(* Logix 5000 project; controller MCMR_v15 vendor 1 type 14 code 51 rev 15.1; software revision 15.02 *)

TASK MainTask (continuous, watchdog 500 ms) : MainProgram

MODULES
   Local : vendor 1 type 14 code 51 (ICP 0, rev 15.1)
      Local_ENBT : 1756-ENBT (Ethernet 105.102.0.224, ICP 3, rev 2.4)
         Remote_ENBT : 1756-ENBT (Ethernet 105.102.0.205, rev 1.6, Output RPI 10 ms)
            MCMR : vendor 1 type 0 code 15 (ICP 1, rev 1.1, Output RPI 5 ms)
END_MODULES

TYPE MCMRBlockStats :   // This object is used to store the block transfer statistics for the MVI56-MCMR module.
STRUCT
   Read : INT;   // Total number of read block transfers
   Write : INT;   // Total number of write block transfers
   Parse : INT;   // Total number of blocks parsed
   Event : INT;   // Total number of event blocks received
   Cmd : INT;   // Total number of command blocks received
   Err : INT;   // Total number of block transfer errors
END_STRUCT
END_TYPE

TYPE MCMRCmdControl :   // Controlling the Modbus Commands
STRUCT
   CmdTrigger : BOOL;   // Command Trigger
   CmdControlData : INT[21];   // Command Control Data
   CmdControlResp : INT[5];   // Command Control Response
   CmdErrTrigger : BOOL;   // Command Error Trigger
   CmdErrData : INT[102];   // Command Error Data
END_STRUCT
END_TYPE

TYPE MCMRCONTROL :   // Tags used for special blocks
STRUCT
   ColdBoot : BOOL;   // Module hardware reset
   WarmBoot : BOOL;   // Module configuration reset
   CmdControlP1 : MCMRCmdControl;   // Command Control for Port 1
   CmdControlP2 : MCMRCmdControl;   // Command Control for Port 2
   EventTriggerP1 : BOOL;   // Triggers the Event Command.
   EventTriggerP2 : BOOL;   // Triggers the Event Command.
   EventCmdP1 : MCMREventCmd[100];   // Event Command for Port 1
   EventCmdP2 : MCMREventCmd[100];   // Event Command for Port 2
   EventCmdRespP1 : INT[5];   // Event Command Response for Port 1
   EventCmdRespP2 : INT[5];   // Event Command Response for Port 2
END_STRUCT
END_TYPE

TYPE MCMRDATA :   // This object contains the Read & Write Data Arrays.
STRUCT
   ReadData : INT[600];   // Data read from module
   WriteData : INT[600];   // Data to write to module
END_STRUCT
END_TYPE

TYPE MCMREventCmd :   // This object is used to contain the attributes to define a master command. An array of these objects is used for each port.
STRUCT
   Enable : INT;   // 0=Disable,1=Continuous,2=Event Command
   IntAddress : INT;   // Module's internal address associated with the command
   PollInt : INT;   // Not used.
   Count : INT;   // Number of registers associated with the command
   Swap : INT;   // Swap code used with command
   Device : INT;   // Device index in Device Table to associate with the command
   Func : INT;   // Function code for the command
   DevAddress : INT;   // Address in device associated with the command
END_STRUCT
END_TYPE

TYPE MCMRInitOutputData :   // Used to bring the Module into a known state after a restart operation.
STRUCT
   InitOutBlkIDLim : INT;   // Block Index Limit for ReadData size of the array
END_STRUCT
END_TYPE

TYPE MCMRModuleDef :   // This object contains variables to be used with the module and status data related to the module.
STRUCT
   DATA : MCMRDATA;   // Read Data and Write Data
   STATUS : MCMRSTATUS;   // Status information in each read block
   CONTROL : MCMRCONTROL;   // Command Control Object
   UTIL : MCMRUTIL;   // Backplane Object
END_STRUCT
END_TYPE

TYPE MCMRPortStats :   // This object is used to store the port statistics for an MVI56-MCMR port.
STRUCT
   PortTrigger : BOOL;   // Triggers port status reading
   CmdReq : INT;   // Total number of command list requests sent
   CmdResp : INT;   // Total number of command list responses received
   CmdErr : INT;   // Total number of command list errors
   Requests : INT;   // Total number of requests for port
   Responses : INT;   // Total number of responses for port
   ErrSent : INT;   // Total number of errors sent
   ErrRec : INT;   // Total number of errors received
   SlaveStats : SINT[250];   // Port Slave status values
END_STRUCT
END_TYPE

TYPE MCMRSTATUS :   // This status data is returned on each read block and can be used to detect proper module operation.
STRUCT
   PassCnt : INT;   // Program cycle counter
   Product : INT[2];   // Product Name
   Rev : INT[2];   // Revision Level Number
   OP : INT[2];   // Operating Level Number
   Run : INT[2];   // Run Number
   Port1Stats : MCMRPortStats;   // Port error statistics for Port 1
   Port2Stats : MCMRPortStats;   // Port error statistics for Port 2
   Block : MCMRBlockStats;   // Block transfer statistics
   Port1CurrentErr : INT;   // Current error/index for Port 1
   Port1LastErr : INT;   // Last error/index for Port 1
   Port2CurrentErr : INT;   // Current error/index for Port 2
   Port2LastErr : INT;   // Last error/index for Port 2
   StatusMsgData : INT[46];   // Triggers status message data
   StatusTrigger : BOOL;   // Triggers Status reading.
END_STRUCT
END_TYPE

TYPE MCMRUTIL :   // This object stores all the variables required for data transfer operation between the module and the controller.
STRUCT
   LastRead : INT;   // Index of last read block
   LastWrite : INT;   // Index of last write block
   BlockIndex : INT;   // Computed block offset for data table
   ReadDataSize : DINT;   // Size of Read Data Array
   WriteDataSize : DINT;   // Size of Write Data Array
   RBTSremainder : INT;   // Computed remainder from Read Data Array size
   WBTSremainder : INT;   // Computed remainder from Write Data Array size
   MaxReadBlock : DINT;   // Maximum read block
   MaxWriteBlock : DINT;   // Maximum write block
   InitOutputData : MCMRInitOutputData;   // This is to initialize output data module reads data from PLC
END_STRUCT
END_TYPE

VAR_GLOBAL   (* controller tags *)
   CmdControlP1_MSG : MESSAGE;
        MessageParameters(ServiceCode := 16#0010, LocalElement := MCMR.CONTROL.CmdControlP1.CmdControlData[0], ...)
   CmdControlP2_MSG : MESSAGE;
        MessageParameters(ServiceCode := 16#0010, LocalElement := MCMR.CONTROL.CmdControlP2.CmdControlData[0], ...)
   CmdControlRespP1_MSG : MESSAGE;
        MessageParameters(ServiceCode := 16#000e, DestinationTag := MCMR.CONTROL.CmdControlP1.CmdControlResp[0], ...)
   CmdControlRespP2_MSG : MESSAGE;
        MessageParameters(ServiceCode := 16#000e, DestinationTag := MCMR.CONTROL.CmdControlP2.CmdControlResp[0], ...)
   CmdErrorP1_MSG : MESSAGE;
        MessageParameters(ServiceCode := 16#000e, DestinationTag := MCMR.CONTROL.CmdControlP1.CmdErrData[0], ...)
   CmdErrorP2_MSG : MESSAGE;
        MessageParameters(ServiceCode := 16#000e, DestinationTag := MCMR.CONTROL.CmdControlP2.CmdErrData[0], ...)
   EventCmdP1_MSG : MESSAGE;
        MessageParameters(ServiceCode := 16#0010, LocalElement := MCMR.CONTROL.EventCmdP1[0], ...)
   EventCmdP2_MSG : MESSAGE;
        MessageParameters(ServiceCode := 16#0010, LocalElement := MCMR.CONTROL.EventCmdP2[0], ...)
   EventCmdRespP1_MSG : MESSAGE;
        MessageParameters(ServiceCode := 16#000e, DestinationTag := MCMR.CONTROL.EventCmdRespP1[0], ...)
   EventCmdRespP2_MSG : MESSAGE;
        MessageParameters(ServiceCode := 16#000e, DestinationTag := MCMR.CONTROL.EventCmdRespP2[0], ...)
   MCMR : MCMRModuleDef;
   MJFAULTS : DINT[12] := ([0] := -731009779, [1] := 207094, [3] := 808632201, [4] := 207000);
   ModuleStatus_MSG : MESSAGE;
        MessageParameters(ServiceCode := 16#000e, DestinationTag := MCMR.STATUS.StatusMsgData[0], ...)
   SlaveStatusP1_MSG : MESSAGE;
        MessageParameters(ServiceCode := 16#000e, DestinationTag := MCMR.STATUS.Port1Stats.SlaveStats[0], ...)
   SlaveStatusP2_MSG : MESSAGE;
        MessageParameters(ServiceCode := 16#000e, DestinationTag := MCMR.STATUS.Port2Stats.SlaveStats[0], ...)
END_VAR

PROGRAM MainProgram   (* main routine MainRoutine *)

ROUTINE MainRoutine   (* ladder *)
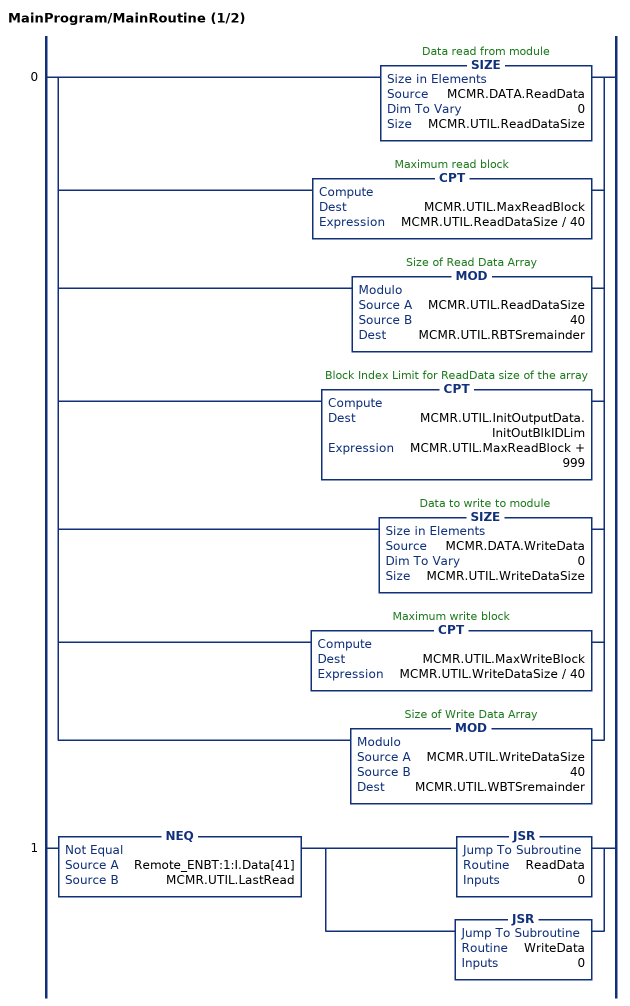
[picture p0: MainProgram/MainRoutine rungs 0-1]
   0: [SIZE(MCMR.DATA.ReadData,0,MCMR.UTIL.ReadDataSize) ,CPT(MCMR.UTIL.MaxReadBlock,MCMR.UTIL.ReadDataSize / 40) ,MOD(MCMR.UTIL.ReadDataSize,40,MCMR.UTIL.RBTSremainder) ,CPT(MCMR.UTIL.InitOutputData.InitOutBlkIDLim,MCMR.UTIL.MaxReadBlock + 999) ,SIZE(MCMR.DATA.WriteData,0,MCMR.UTIL.WriteDataSize) ,CPT(MCMR.UTIL.MaxWriteBlock,MCMR.UTIL.WriteDataSize / 40) ,MOD(MCMR.UTIL.WriteDataSize,40,MCMR.UTIL.WBTSremainder) ];
   1: NEQ(Remote_ENBT:1:I.Data[41],MCMR.UTIL.LastRead)[JSR(ReadData,0) ,JSR(WriteData,0) ];
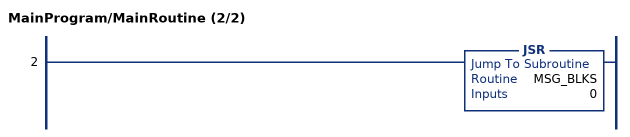
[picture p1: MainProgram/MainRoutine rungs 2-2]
   2: JSR(MSG_BLKS,0);
END_ROUTINE

ROUTINE MSG_BLKS   (* ladder *)
// This routine handles all the MSG blocks used by the MCMR module
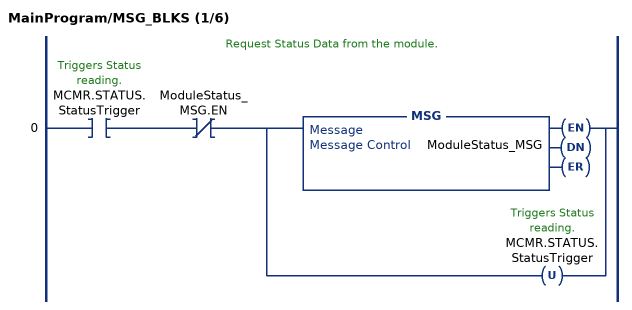
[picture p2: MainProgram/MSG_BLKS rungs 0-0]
   // Request Status Data from the module.
   0: XIC(MCMR.STATUS.StatusTrigger)XIO(ModuleStatus_MSG.EN)[MSG(ModuleStatus_MSG) ,OTU(MCMR.STATUS.StatusTrigger) ];
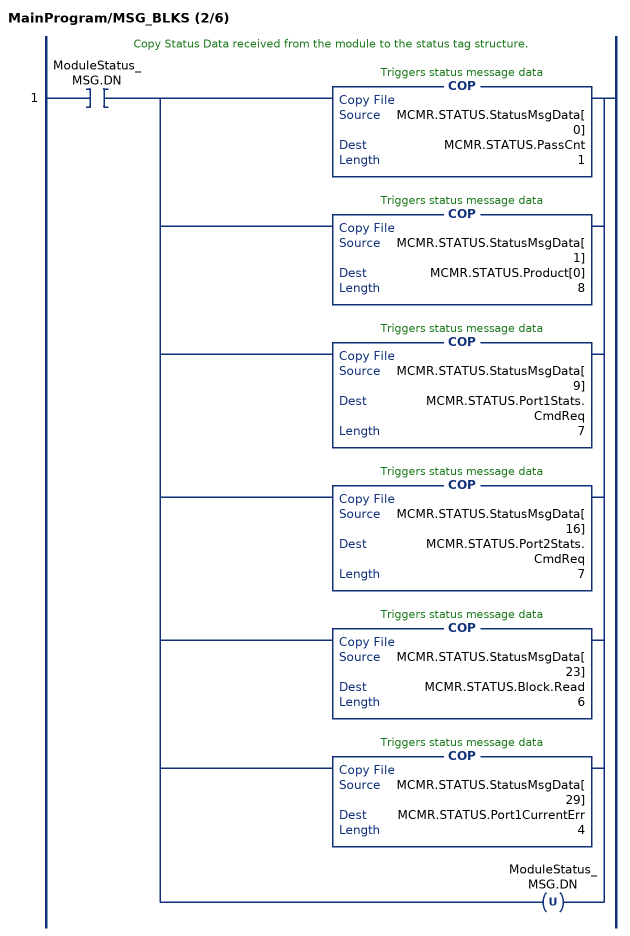
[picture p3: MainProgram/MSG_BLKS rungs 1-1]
   // Copy Status Data received from the module to the status tag structure.
   1: XIC(ModuleStatus_MSG.DN)[COP(MCMR.STATUS.StatusMsgData[0],MCMR.STATUS.PassCnt,1) ,COP(MCMR.STATUS.StatusMsgData[1],MCMR.STATUS.Product[0],8) ,COP(MCMR.STATUS.StatusMsgData[9],MCMR.STATUS.Port1Stats.CmdReq,7) ,COP(MCMR.STATUS.StatusMsgData[16],MCMR.STATUS.Port2Stats.CmdReq,7) ,COP(MCMR.STATUS.StatusMsgData[23],MCMR.STATUS.Block.Read,6) ,COP(MCMR.STATUS.StatusMsgData[29],MCMR.STATUS.Port1CurrentErr,4) ,OTU(ModuleStatus_MSG.DN) ];
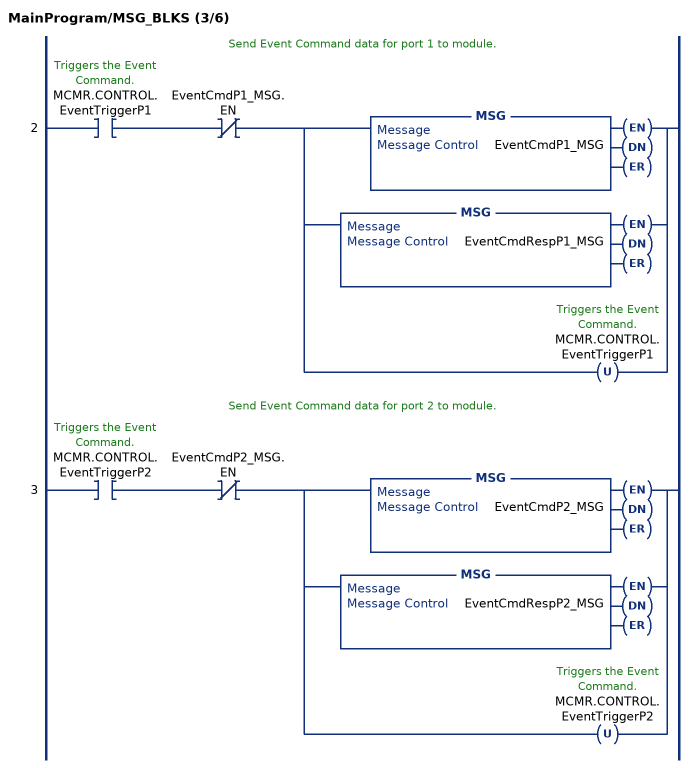
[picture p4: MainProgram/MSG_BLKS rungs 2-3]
   // Send Event Command data for port 1 to module.
   2: XIC(MCMR.CONTROL.EventTriggerP1)XIO(EventCmdP1_MSG.EN)[MSG(EventCmdP1_MSG) ,MSG(EventCmdRespP1_MSG) ,OTU(MCMR.CONTROL.EventTriggerP1) ];
   // Send Event Command data for port 2 to module.
   3: XIC(MCMR.CONTROL.EventTriggerP2)XIO(EventCmdP2_MSG.EN)[[MSG(EventCmdP2_MSG) ,MSG(EventCmdRespP2_MSG) ] ,OTU(MCMR.CONTROL.EventTriggerP2) ];
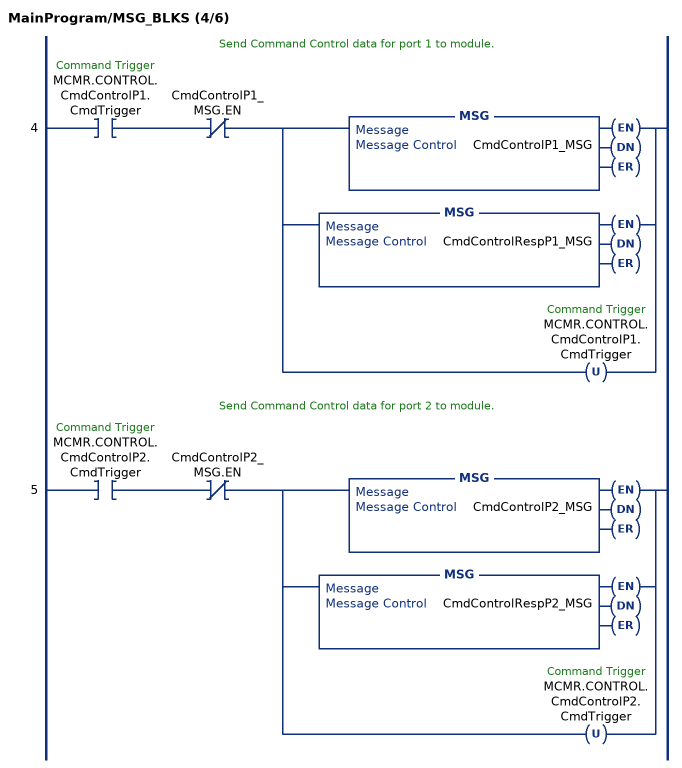
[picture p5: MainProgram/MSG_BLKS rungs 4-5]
   // Send Command Control data for port 1 to module.
   4: XIC(MCMR.CONTROL.CmdControlP1.CmdTrigger)XIO(CmdControlP1_MSG.EN)[[MSG(CmdControlP1_MSG) ,MSG(CmdControlRespP1_MSG) ] ,OTU(MCMR.CONTROL.CmdControlP1.CmdTrigger) ];
   // Send Command Control data for port 2 to module.
   5: XIC(MCMR.CONTROL.CmdControlP2.CmdTrigger)XIO(CmdControlP2_MSG.EN)[[MSG(CmdControlP2_MSG) ,MSG(CmdControlRespP2_MSG) ] ,OTU(MCMR.CONTROL.CmdControlP2.CmdTrigger) ];
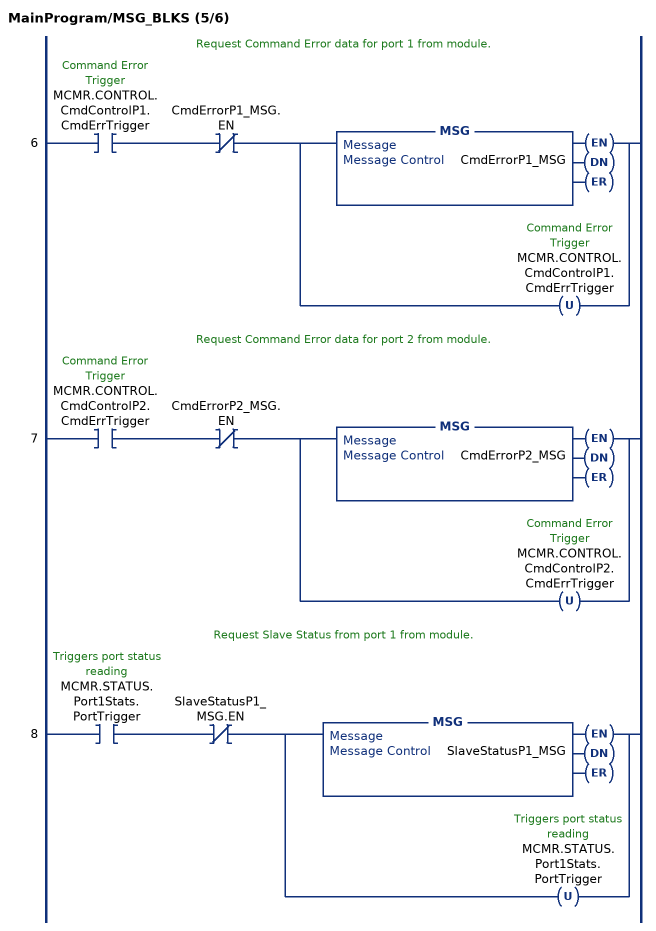
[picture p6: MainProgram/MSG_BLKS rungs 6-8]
   // Request Command Error data for port 1 from module.
   6: XIC(MCMR.CONTROL.CmdControlP1.CmdErrTrigger)XIO(CmdErrorP1_MSG.EN)[MSG(CmdErrorP1_MSG) ,OTU(MCMR.CONTROL.CmdControlP1.CmdErrTrigger) ];
   // Request Command Error data for port 2 from module.
   7: XIC(MCMR.CONTROL.CmdControlP2.CmdErrTrigger)XIO(CmdErrorP2_MSG.EN)[MSG(CmdErrorP2_MSG) ,OTU(MCMR.CONTROL.CmdControlP2.CmdErrTrigger) ];
   // Request Slave Status from port 1 from module.
   8: XIC(MCMR.STATUS.Port1Stats.PortTrigger)XIO(SlaveStatusP1_MSG.EN)[MSG(SlaveStatusP1_MSG) ,OTU(MCMR.STATUS.Port1Stats.PortTrigger) ];
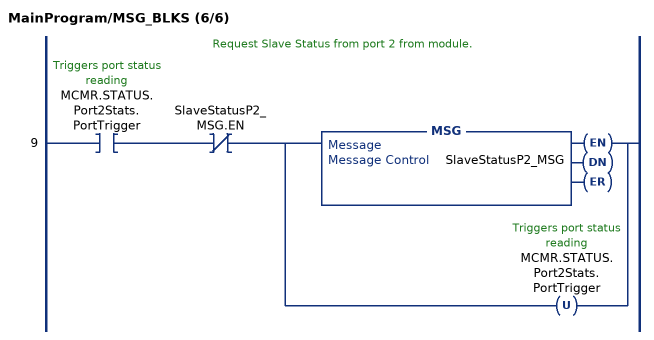
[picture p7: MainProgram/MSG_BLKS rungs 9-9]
   // Request Slave Status from port 2 from module.
   9: XIC(MCMR.STATUS.Port2Stats.PortTrigger)XIO(SlaveStatusP2_MSG.EN)[MSG(SlaveStatusP2_MSG) ,OTU(MCMR.STATUS.Port2Stats.PortTrigger) ];
END_ROUTINE

ROUTINE ReadData   (* ladder *)
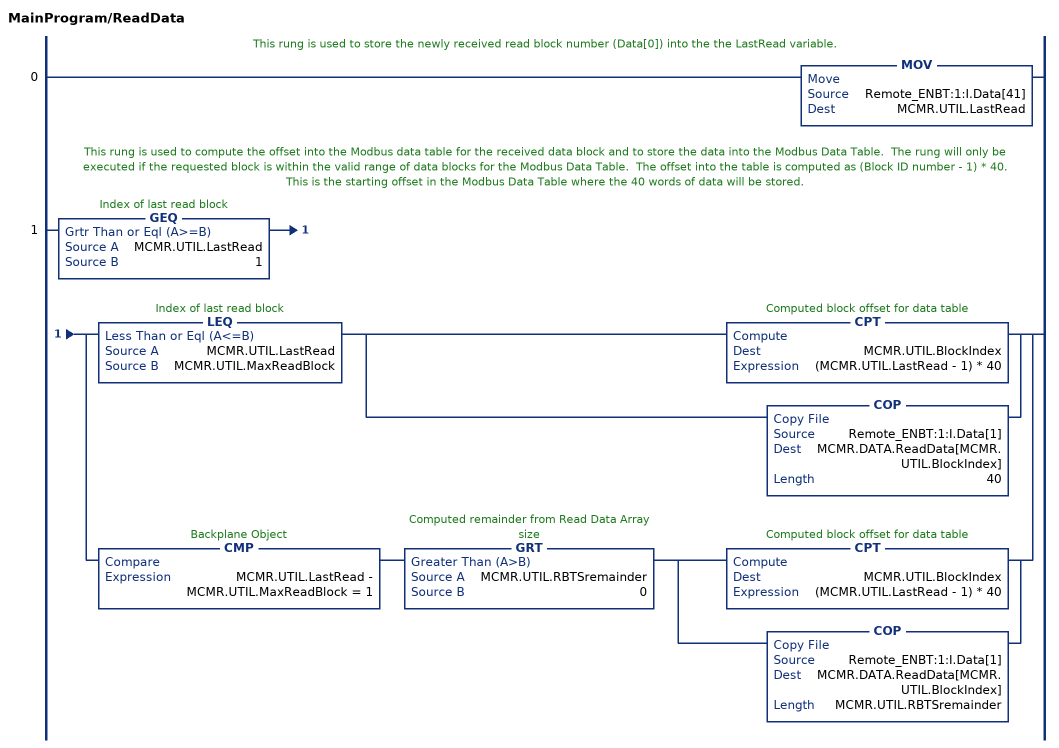
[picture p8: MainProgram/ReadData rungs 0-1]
   // This rung is used to store the newly received read block number (Data[0]) into the the LastRead variable.
   0: MOV(Remote_ENBT:1:I.Data[41],MCMR.UTIL.LastRead);
   // This rung is used to compute the offset into the Modbus data table for the received data block and to store the data into the Modbus Data Table.  The rung will only be executed if the requested block is within the valid range of data blocks for the Modbus Data Table.  The offset into the table is computed as (Block ID number - 1) * 40.  This is the starting offset in the Modbus Data Table where the 40 words of data will be stored.
   1: GEQ(MCMR.UTIL.LastRead,1)[LEQ(MCMR.UTIL.LastRead,MCMR.UTIL.MaxReadBlock) [CPT(MCMR.UTIL.BlockIndex,(MCMR.UTIL.LastRead - 1) * 40) ,COP(Remote_ENBT:1:I.Data[1],MCMR.DATA.ReadData[MCMR.UTIL.BlockIndex],40) ] ,CMP(MCMR.UTIL.LastRead - MCMR.UTIL.MaxReadBlock = 1) GRT(MCMR.UTIL.RBTSremainder,0) [CPT(MCMR.UTIL.BlockIndex,(MCMR.UTIL.LastRead - 1) * 40) ,COP(Remote_ENBT:1:I.Data[1],MCMR.DATA.ReadData[MCMR.UTIL.BlockIndex],MCMR.UTIL.RBTSremainder) ] ];
END_ROUTINE

ROUTINE WriteData   (* ladder *)
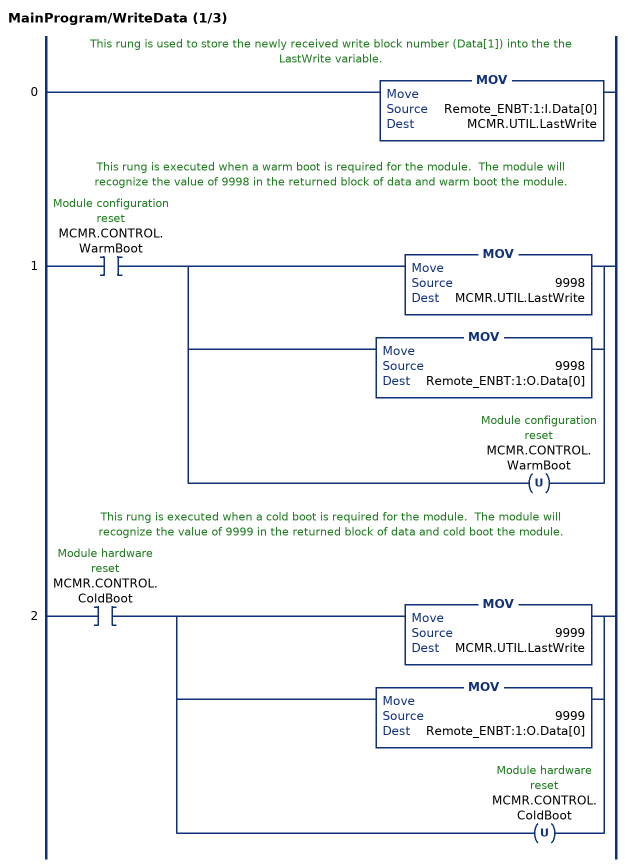
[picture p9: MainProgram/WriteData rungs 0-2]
   // This rung is used to store the newly received write block number (Data[1]) into the the LastWrite variable.
   0: MOV(Remote_ENBT:1:I.Data[0],MCMR.UTIL.LastWrite);
   // This rung is executed when a warm boot is required for the module.  The module will recognize the value of 9998 in the returned block of data and warm boot the module.
   1: XIC(MCMR.CONTROL.WarmBoot)[MOV(9998,MCMR.UTIL.LastWrite) ,MOV(9998,Remote_ENBT:1:O.Data[0]) ,OTU(MCMR.CONTROL.WarmBoot) ];
   // This rung is executed when a cold boot is required for the module.  The module will recognize the value of 9999 in the returned block of data and cold boot the module.
   2: XIC(MCMR.CONTROL.ColdBoot)[MOV(9999,MCMR.UTIL.LastWrite) ,MOV(9999,Remote_ENBT:1:O.Data[0]) ,OTU(MCMR.CONTROL.ColdBoot) ];
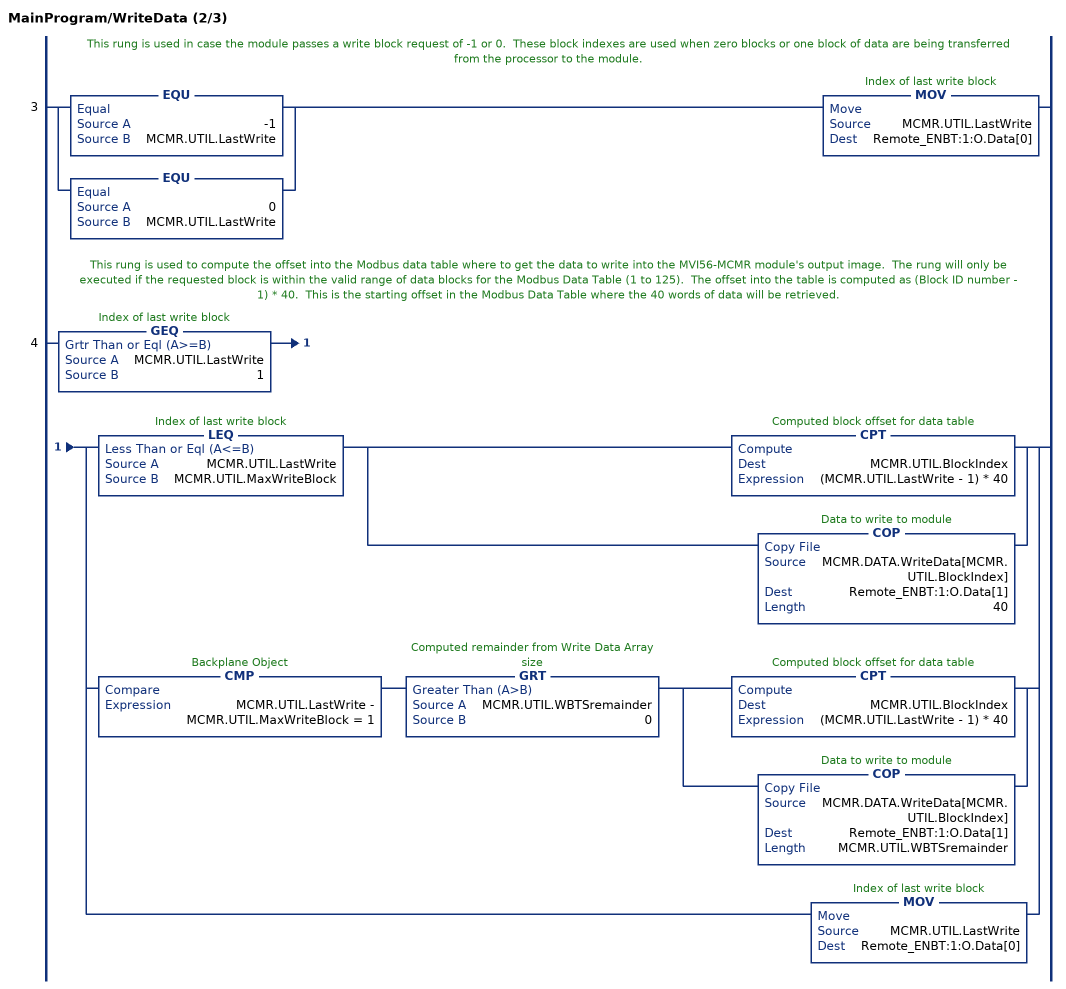
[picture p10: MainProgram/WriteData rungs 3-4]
   // This rung is used in case the module passes a write block request of -1 or 0.  These block indexes are used when zero blocks or one block of data are being transferred from the processor to the module.
   3: [EQU(-1,MCMR.UTIL.LastWrite) ,EQU(0,MCMR.UTIL.LastWrite) ]MOV(MCMR.UTIL.LastWrite,Remote_ENBT:1:O.Data[0]);
   // This rung is used to compute the offset into the Modbus data table where to get the data to write into the MVI56-MCMR module's output image.  The rung will only be executed if the requested block is within the valid range of data blocks for the Modbus Data Table (1 to 125).  The offset into the table is computed as (Block ID number - 1) * 40.  This is the starting offset in the Modbus Data Table where the 40 words of data will be retrieved.
   4: GEQ(MCMR.UTIL.LastWrite,1)[LEQ(MCMR.UTIL.LastWrite,MCMR.UTIL.MaxWriteBlock) [CPT(MCMR.UTIL.BlockIndex,(MCMR.UTIL.LastWrite - 1) * 40) ,COP(MCMR.DATA.WriteData[MCMR.UTIL.BlockIndex],Remote_ENBT:1:O.Data[1],40) ] ,CMP(MCMR.UTIL.LastWrite - MCMR.UTIL.MaxWriteBlock = 1) GRT(MCMR.UTIL.WBTSremainder,0) [CPT(MCMR.UTIL.BlockIndex,(MCMR.UTIL.LastWrite - 1) * 40) ,COP(MCMR.DATA.WriteData[MCMR.UTIL.BlockIndex],Remote_ENBT:1:O.Data[1],MCMR.UTIL.WBTSremainder) ] ,MOV(MCMR.UTIL.LastWrite,Remote_ENBT:1:O.Data[0]) ];
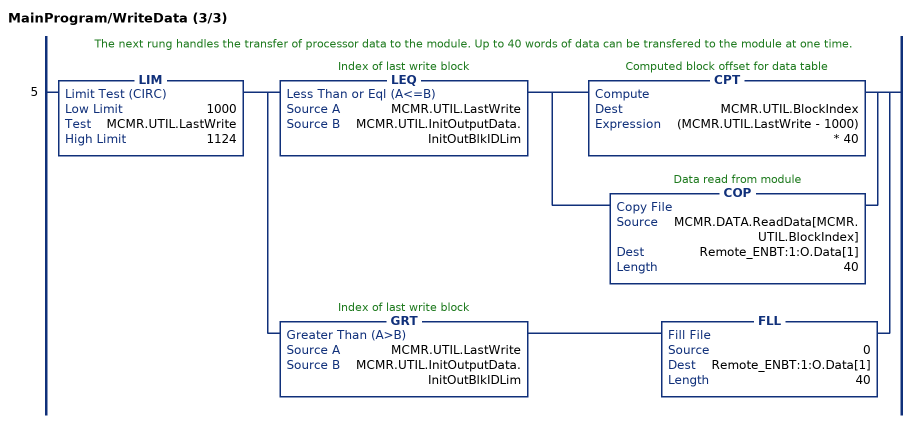
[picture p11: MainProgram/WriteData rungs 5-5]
   // The next rung handles the transfer of processor data to the module. Up to 40 words of data can be transfered to the module at one time.
   5: LIM(1000,MCMR.UTIL.LastWrite,1124)[LEQ(MCMR.UTIL.LastWrite,MCMR.UTIL.InitOutputData.InitOutBlkIDLim) [CPT(MCMR.UTIL.BlockIndex,(MCMR.UTIL.LastWrite - 1000) * 40) ,COP(MCMR.DATA.ReadData[MCMR.UTIL.BlockIndex],Remote_ENBT:1:O.Data[1],40) ] ,GRT(MCMR.UTIL.LastWrite,MCMR.UTIL.InitOutputData.InitOutBlkIDLim) FLL(0,Remote_ENBT:1:O.Data[1],40) ];
END_ROUTINE
END_PROGRAM

PROGRAM StartUp   (* main routine PowerUp *)

ROUTINE PowerUp   (* ladder *)
// This routine is executed each time the module is powered up or restarted.
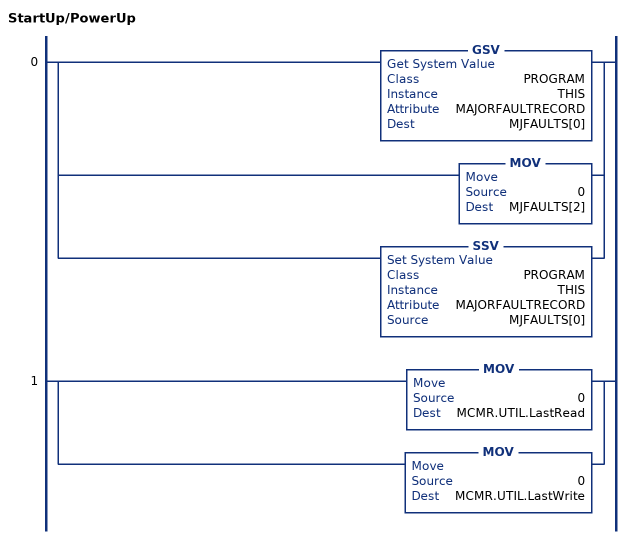
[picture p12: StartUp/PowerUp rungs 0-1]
   0: [GSV(PROGRAM,THIS,MAJORFAULTRECORD,MJFAULTS[0]) ,MOV(0,MJFAULTS[2]) ,SSV(PROGRAM,THIS,MAJORFAULTRECORD,MJFAULTS[0]) ];
   1: [MOV(0,MCMR.UTIL.LastRead) ,MOV(0,MCMR.UTIL.LastWrite) ];
END_ROUTINE
END_PROGRAM
